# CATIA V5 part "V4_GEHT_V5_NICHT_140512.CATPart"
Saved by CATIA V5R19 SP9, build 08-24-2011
Part number: V4_geht_V5_nicht_140512
Bounding box of the stored display mesh (mm): x 1898.187 to 2212.859, y -916.661 to -551.702, z 941.827 to 1204.862
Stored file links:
  K:\KonstrukteureBaer\2012\ROA\Problembehandlung_V4_V5\CAD_Modell\V4_GEHT_V5_NICHT_140512.CATPart
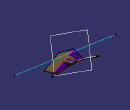
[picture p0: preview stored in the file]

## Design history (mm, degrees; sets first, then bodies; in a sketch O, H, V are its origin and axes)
AxisSystem1: origin (0, 0, 0), X (1, 0, 0), Y (0, 1, 0), Z (0, 0, 1)
Set1 "hilfsgeo"
  Plane1 "Schnittplane": stored without definition
  Line1 "Spine": stored without definition
  Intersect1: ToIntersect1 Plane1, ToIntersect2 DatumSurface4
Set2 "Grundflaechen"
  DatumSurface1 to DatumSurface4
  Split1: ToCut DatumSurface4, Cutting Intersect1
Set3 "Flaechen_V5"
  Fillet1: type BiTangent, Element1 DatumSurface4, Element2 DatumSurface1, Radius 10, Spine Line1, HoldCurve Intersect1
  Fillet2: type BiTangent, Element1 DatumSurface4, Element2 DatumSurface3, Radius 10, Spine Line1, HoldCurve Intersect1
Set4 "Flaechen_V4"
  DatumSurface5 to DatumSurface7
Body1 (main body)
